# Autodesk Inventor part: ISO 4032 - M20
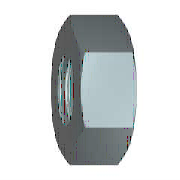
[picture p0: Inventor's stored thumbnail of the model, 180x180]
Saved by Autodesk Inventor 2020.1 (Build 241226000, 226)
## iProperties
Manager: www.cadconsulting.pl
Company: Fabian Stasiak CAD Consulting
Created: 2006-02
Part Number: ISO 4032 - M20
Material: Stal, miękka
Description: Nakrętka
Document SubType Name: Modeling
Standard: ISO 4032
Designer: F.Stasiak
Standards Organization: DIN
Language: pl-PL
Size Designation: M20
Categories: <MemberInstance><Categories><Category DisplayName="Mocowania" InternalName="e4da775c-781d-43d5-af7c-5136215cf5a6" Mnemonic="FSTN"><Category DisplayName="Nakrętk
Density: 7.85 g/cm^3
Appearance: Stal
Mass: 74.6998 g
Surface Area: 36.9844 cm^2
Volume: 9.5159 cm^3
Author: F.Stasiak
Subject: Zbiór ćwiczeń. Autodesk Inventor 2020. Kurs podstawowy
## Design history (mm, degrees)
sketch "Szkic1"
  geometry: L1 (-17.321, 0)-(-8.66, 15); L2 (-8.66, 15)-(8.66, 15); L3 (8.66, 15)-(17.321, 0); L4 (17.321, 0)-(8.66, -15); L5 (8.66, -15)-(-8.66, -15); L6 (-8.66, -15)-(-17.321, 0); 2 further points
  constraints: 12 end point, 1 coincident, 1 horizontal, 11 other
  dimensions: "d0" = 34.64102 distance of L3.end L1.start (= 1.1547 x SW)
extrude "Bryła" new body sketch "Szkic1" distance "d1" = 18 (= KOH); taper "d2" = 0 deg
sketch "Szkic2"
  geometry: L1 (0, 8.66)-(0, 17.321) reference; L2 (0, 17.321)-(18, 17.321) reference; L3 (18, 8.66)-(18, 17.321) reference; L4 (-1.8, 0)-(23.4, 0) reference; L5 (2.004, 17.321)-(0, 13.85); L6 (15.996, 17.321)-(18, 13.85)
  constraints: 4 end point, 4 point on line
  dimensions: "d3" = 30 deg angle of L1 L5 (= ANG1); "d4" = 30 deg angle of L3 L6 (= ANG2); "d5" = 27.7 diameter of L5.end L4 (= SW0); "d6" = 27.7 diameter of L6.end L4 (= SW01)
revolve "Faza1" sketch "Szkic2" stored, may be unused: angle "d7" = 90 deg
sketch "Szkic3"
  geometry: 4 further points
  constraints: 1 coincident, 1 other
hole "Gwint" sketch "Szkic3" at (0, 0) diameter "d25" = 17.294; stored, may be unused: countersink angle "d29" = 82 deg, drill point angle "d31" = 118 deg; dims "d26" = 6, "d27" = 4, "d28" = 2, "d30" = 8
workaxis "Work Axis1"
workplane "Work Plane1"
node "Bryła1"
node "Korpusy bryłowe"
node "Korpusy powierzchniowe"
chamfer "Faza2" distance "d8" = 1.35316 (= -0.5 x GD1 + 0.5 x NND); stored, may be unused: angle "d9" = 30 deg, second distance "d40" = 1.35316 (= -0.5 x GD1 + 0.5 x NND)
chamfer "Faza3" distance "d10" = 1.35316 (= -0.5 x GD1 + 0.5 x NND); stored, may be unused: angle "d11" = 30 deg, second distance "d41" = 1.35316 (= -0.5 x GD1 + 0.5 x NND)
other parameters: "ANG1" = 30 deg [user parameter; used in 1 equation term], "ANG2" = 30 deg [user parameter; used in 1 equation term], "KOH" = 18 [user parameter; used in 1 equation term], "SW0" = 27.7 [user parameter; used in 1 equation term], "SW01" = 27.7 [user parameter; used in 1 equation term], "GD1" = 17.29367 (computed from THREADDIA, PTC, TOA) [user parameter; used in 4 equation terms], "d13" = 0, "d14" = 0, "d39" = 0, "d42" = 0, "GUL" = 1.35317 (= 0.541266 x PTC) [user parameter], "TPU" = 4 (computed from PTC) [user parameter], "TOA" = 30 deg [user parameter; used in 1 equation term], "PTC" = 2.5 [user parameter; used in 4 equation terms], "E0" = 34.65 (= 1.155 x SW) [user parameter], "GAL" = 1.35317 (= 0.541266 x PTC) [user parameter]
